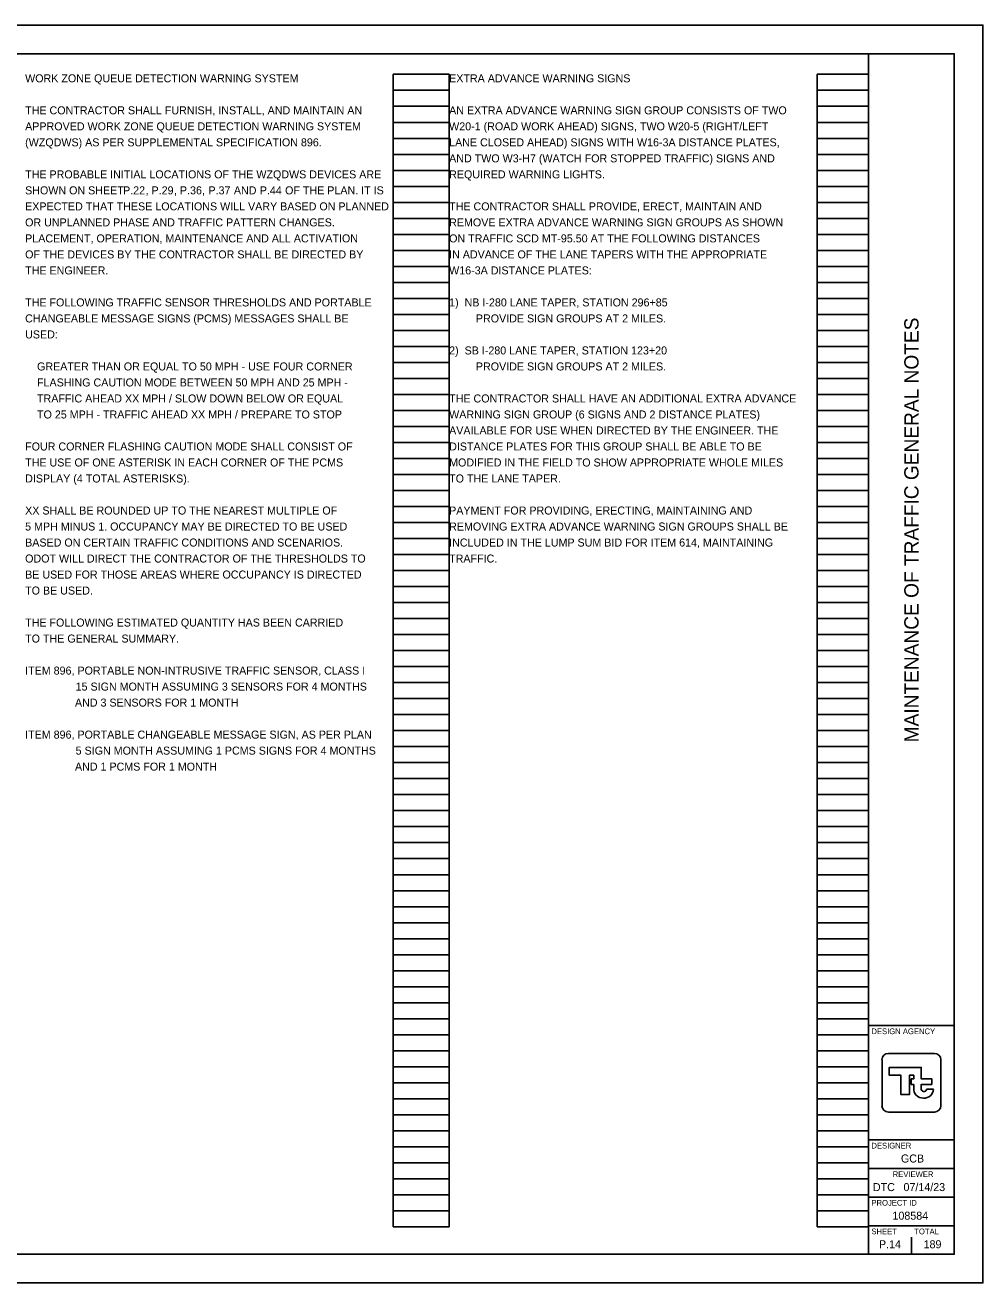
# Model space of a CAD drawing. Extents: x -33.9 to 34, y -0.4 to 22.
# Drawn here: x 17.24 to 34, y 0 to 22 of the extents above; entities that cross this region are included whole.
import ezdxf

# ---------------------------------------------------------------- set-up
doc = ezdxf.new("R2010")
doc.units = 0
for name, color, linetype in [('SH_Border', 7, 'Continuous'), ('SH_Cut_Line', 7, 'Continuous'), ('SH_Data', 7, 'Continuous'), ('SH_Text', 7, 'Continuous')]:
    doc.layers.add(name, color=color, linetype=linetype)

msp = doc.modelspace()

# ---------------------------------------------------------------- linework, layer by layer
at = {"layer": 'SH_Border'}
for p, q in [((32, 0.5), (32, 21.5)), ((32, 4.5), (33.5, 4.5)), ((32, 2.5), (33.5, 2.5)), ((32, 2), (33.5, 2)), ((32, 1.5), (33.5, 1.5)), ((32, 1), (33.5, 1))]:
    msp.add_line(p, q, dxfattribs=at)
msp.add_lwpolyline([(1.5, 21.5), (33.5, 21.5), (33.5, 0.5), (1.5, 0.5)], close=True, dxfattribs=at)
at = {"layer": 'SH_Cut_Line'}
msp.add_lwpolyline([(0, 0), (34, 0), (34, 22), (0, 22)], close=True, dxfattribs=at)
at = {"layer": 'SH_Data'}
for p, q in [((23.68, 0.98), (23.68, 21.14)), ((23.68, 21.14), (24.66, 21.14)), ((24.66, 0.98), (24.66, 21.14)), ((31.1, 0.98), (31.1, 21.14)), ((31.1, 21.14), (32, 21.14)), ((32, 0.98), (32, 21.14)), ((23.68, 20.86), (24.66, 20.86)), ((31.1, 20.86), (32, 20.86)), ((23.68, 20.58), (24.66, 20.58)), ((31.1, 20.58), (32, 20.58)), ((23.68, 20.3), (24.66, 20.3)), ((31.1, 20.3), (32, 20.3)), ((23.68, 20.02), (24.66, 20.02)), ((31.1, 20.02), (32, 20.02)), ((23.68, 19.74), (24.66, 19.74)), ((31.1, 19.74), (32, 19.74)), ((23.68, 19.46), (24.66, 19.46)), ((31.1, 19.46), (32, 19.46)), ((23.68, 19.18), (24.66, 19.18)), ((31.1, 19.18), (32, 19.18)), ((23.68, 18.9), (24.66, 18.9)), ((31.1, 18.9), (32, 18.9)), ((23.68, 18.62), (24.66, 18.62)), ((31.1, 18.62), (32, 18.62)), ((23.68, 18.34), (24.66, 18.34)), ((31.1, 18.34), (32, 18.34)), ((23.68, 18.06), (24.66, 18.06)), ((31.1, 18.06), (32, 18.06)), ((23.68, 17.78), (24.66, 17.78)), ((31.1, 17.78), (32, 17.78)), ((23.68, 17.5), (24.66, 17.5)), ((31.1, 17.5), (32, 17.5)), ((23.68, 17.22), (24.66, 17.22)), ((31.1, 17.22), (32, 17.22)), ((23.68, 16.94), (24.66, 16.94)), ((31.1, 16.94), (32, 16.94)), ((23.68, 16.66), (24.66, 16.66)), ((31.1, 16.66), (32, 16.66)), ((23.68, 16.38), (24.66, 16.38)), ((31.1, 16.38), (32, 16.38)), ((23.68, 16.1), (24.66, 16.1)), ((31.1, 16.1), (32, 16.1)), ((23.68, 15.82), (24.66, 15.82)), ((31.1, 15.82), (32, 15.82)), ((23.68, 15.54), (24.66, 15.54)), ((31.1, 15.54), (32, 15.54)), ((23.68, 15.26), (24.66, 15.26)), ((31.1, 15.26), (32, 15.26)), ((23.68, 14.98), (24.66, 14.98)), ((31.1, 14.98), (32, 14.98)), ((23.68, 14.7), (24.66, 14.7)), ((31.1, 14.7), (32, 14.7)), ((23.68, 14.42), (24.66, 14.42)), ((31.1, 14.42), (32, 14.42)), ((23.68, 14.14), (24.66, 14.14)), ((31.1, 14.14), (32, 14.14)), ((23.68, 13.86), (24.66, 13.86)), ((31.1, 13.86), (32, 13.86)), ((23.68, 13.58), (24.66, 13.58)), ((31.1, 13.58), (32, 13.58)), ((23.68, 13.3), (24.66, 13.3)), ((31.1, 13.3), (32, 13.3)), ((23.68, 13.02), (24.66, 13.02)), ((31.1, 13.02), (32, 13.02)), ((23.68, 12.74), (24.66, 12.74)), ((31.1, 12.74), (32, 12.74)), ((23.68, 12.46), (24.66, 12.46)), ((31.1, 12.46), (32, 12.46)), ((23.68, 12.18), (24.66, 12.18)), ((31.1, 12.18), (32, 12.18)), ((23.68, 11.9), (24.66, 11.9)), ((31.1, 11.9), (32, 11.9)), ((23.68, 11.62), (24.66, 11.62)), ((31.1, 11.62), (32, 11.62)), ((23.68, 11.34), (24.66, 11.34)), ((31.1, 11.34), (32, 11.34)), ((23.68, 11.06), (24.66, 11.06)), ((31.1, 11.06), (32, 11.06)), ((23.68, 10.78), (24.66, 10.78)), ((31.1, 10.78), (32, 10.78)), ((23.68, 10.5), (24.66, 10.5)), ((31.1, 10.5), (32, 10.5)), ((23.68, 10.22), (24.66, 10.22)), ((31.1, 10.22), (32, 10.22)), ((23.68, 9.94), (24.66, 9.94)), ((31.1, 9.94), (32, 9.94)), ((23.68, 9.66), (24.66, 9.66)), ((31.1, 9.66), (32, 9.66)), ((23.68, 9.38), (24.66, 9.38)), ((31.1, 9.38), (32, 9.38)), ((23.68, 9.1), (24.66, 9.1)), ((31.1, 9.1), (32, 9.1)), ((23.68, 8.82), (24.66, 8.82)), ((31.1, 8.82), (32, 8.82)), ((23.68, 8.54), (24.66, 8.54)), ((31.1, 8.54), (32, 8.54)), ((23.68, 8.26), (24.66, 8.26)), ((31.1, 8.26), (32, 8.26)), ((23.68, 7.98), (24.66, 7.98)), ((31.1, 7.98), (32, 7.98)), ((23.68, 7.7), (24.66, 7.7)), ((31.1, 7.7), (32, 7.7)), ((23.68, 7.42), (24.66, 7.42)), ((31.1, 7.42), (32, 7.42)), ((23.68, 7.14), (24.66, 7.14)), ((31.1, 7.14), (32, 7.14)), ((23.68, 6.86), (24.66, 6.86)), ((31.1, 6.86), (32, 6.86)), ((23.68, 6.58), (24.66, 6.58)), ((31.1, 6.58), (32, 6.58)), ((23.68, 6.3), (24.66, 6.3)), ((31.1, 6.3), (32, 6.3)), ((23.68, 6.02), (24.66, 6.02)), ((31.1, 6.02), (32, 6.02)), ((23.68, 5.74), (24.66, 5.74)), ((31.1, 5.74), (32, 5.74)), ((23.68, 5.46), (24.66, 5.46)), ((31.1, 5.46), (32, 5.46)), ((23.68, 5.18), (24.66, 5.18)), ((31.1, 5.18), (32, 5.18)), ((23.68, 4.9), (24.66, 4.9)), ((31.1, 4.9), (32, 4.9)), ((23.68, 4.62), (24.66, 4.62)), ((31.1, 4.62), (32, 4.62)), ((23.68, 4.34), (24.66, 4.34)), ((31.1, 4.34), (32, 4.34)), ((23.68, 4.06), (24.66, 4.06)), ((31.1, 4.06), (32, 4.06)), ((23.68, 3.78), (24.66, 3.78)), ((31.1, 3.78), (32, 3.78)), ((23.68, 3.5), (24.66, 3.5)), ((31.1, 3.5), (32, 3.5)), ((32.75, 3.5), (32.75, 3.5)), ((32.791, 3.415), (32.791, 3.415)), ((33.136, 3.385), (33.015, 3.385)), ((23.68, 3.22), (24.66, 3.22)), ((31.1, 3.22), (32, 3.22)), ((23.68, 2.94), (24.66, 2.94)), ((31.1, 2.94), (32, 2.94)), ((23.68, 2.66), (24.66, 2.66)), ((31.1, 2.66), (32, 2.66)), ((23.68, 2.38), (24.66, 2.38)), ((31.1, 2.38), (32, 2.38)), ((23.68, 2.1), (24.66, 2.1)), ((31.1, 2.1), (32, 2.1)), ((23.68, 1.82), (24.66, 1.82)), ((31.1, 1.82), (32, 1.82)), ((23.68, 1.54), (24.66, 1.54)), ((31.1, 1.54), (32, 1.54)), ((23.68, 1.26), (24.66, 1.26)), ((31.1, 1.26), (32, 1.26)), ((23.68, 0.98), (24.66, 0.98)), ((31.1, 0.98), (32, 0.98)), ((32.375, 0.675), (32.375, 0.675)), ((32.75, 0.5), (32.75, 0.8))]:
    msp.add_line(p, q, dxfattribs=at)
for points in [[(32.348, 4.014), (33.152, 4.014)], [(32.236, 3.099), (32.236, 3.901)], [(32.922, 3.399), (32.922, 3.47), (33.107, 3.47), (33.107, 3.568), (32.922, 3.568), (32.922, 3.768), (32.361, 3.768), (32.361, 3.632), (32.566, 3.632), (32.566, 3.294), (32.715, 3.294), (32.715, 3.63), (32.79, 3.63), (32.79, 3.568), (32.748, 3.568), (32.748, 3.47), (32.79, 3.47), (32.79, 3.415), (32.791, 3.415)], [(33.264, 3.901), (33.264, 3.099)], [(33.152, 2.986), (32.348, 2.986)]]:
    msp.add_lwpolyline(points, dxfattribs=at)
for centre, radius, start, end in [((32.348, 3.901), 0.113, 90, 180), ((33.152, 3.901), 0.113, 360, 90), ((32.949, 3.392), 0.16, 171.8856, 274.8323), ((32.968, 3.392), 0.0473, 171.8856, 350.9243), ((32.976, 3.392), 0.16, 265.1677, 357.3201), ((32.348, 3.099), 0.113, 180, 270), ((33.152, 3.099), 0.113, 270, 360)]:
    msp.add_arc(centre, radius, start, end, dxfattribs=at)

# ---------------------------------------------------------------- texts
msp.add_text('MAINTENANCE OF TRAFFIC GENERAL NOTES', height=0.25, rotation=90, dxfattribs=at).set_placement((32.875, 9.455))
for s, height, p in [('DESIGN AGENCY', 0.1, (32.05, 4.35)), ('DESIGNER', 0.1, (32.05, 2.35)), ('GCB', 0.14, (32.566, 2.105)), ('REVIEWER', 0.1, (32.422, 1.85)), ('DTC', 0.14, (32.076, 1.605)), ('07/14/23', 0.14, (32.611, 1.605)), ('PROJECT ID', 0.1, (32.05, 1.35)), ('108584', 0.14, (32.418, 1.105)), ('SHEET', 0.1, (32.05, 0.85)), ('TOTAL', 0.1, (32.8, 0.85)), ('P.14', 0.14, (32.182, 0.605)), ('189', 0.14, (32.963, 0.605))]:
    msp.add_text(s, height=height, dxfattribs=at).set_placement(p)
at = {"layer": 'SH_Text'}
for s, p in [('WORK ZONE QUEUE DETECTION WARNING SYSTEM', (17.24, 21)), ('EXTRA ADVANCE WARNING SIGNS', (24.66, 21)), ('THE CONTRACTOR SHALL FURNISH, INSTALL, AND MAINTAIN AN', (17.24, 20.44)), ('AN EXTRA ADVANCE WARNING SIGN GROUP CONSISTS OF TWO', (24.66, 20.44)), ('APPROVED WORK ZONE QUEUE DETECTION WARNING SYSTEM', (17.24, 20.16)), ('W20-1 (ROAD WORK AHEAD) SIGNS, TWO W20-5 (RIGHT/LEFT', (24.66, 20.16)), ('(WZQDWS) AS PER SUPPLEMENTAL SPECIFICATION 896.', (17.24, 19.88)), ('LANE CLOSED AHEAD) SIGNS WITH W16-3A DISTANCE PLATES,', (24.66, 19.88)), ('AND TWO W3-H7 (WATCH FOR STOPPED TRAFFIC) SIGNS AND', (24.66, 19.6)), ('THE PROBABLE INITIAL LOCATIONS OF THE WZQDWS DEVICES ARE', (17.24, 19.32)), ('REQUIRED WARNING LIGHTS.', (24.66, 19.32)), ('SHOWN ON SHEET ', (17.24, 19.04)), ('P.22', (18.954, 19.04)), ('P.29', (19.452, 19.04)), (', P.36, ', (19.845, 19.04)), ('P.37', (20.448, 19.04)), (' AND ', (20.841, 19.04)), ('P.44', (21.346, 19.04)), ('OF THE PLAN. IT IS ', (21.789, 19.04)), (', ', (19.347, 19.04)), ('EXPECTED THAT THESE LOCATIONS WILL VARY BASED ON PLANNED', (17.24, 18.76)), ('THE CONTRACTOR SHALL PROVIDE, ERECT, MAINTAIN AND', (24.66, 18.76)), ('OR UNPLANNED PHASE AND TRAFFIC PATTERN CHANGES.', (17.24, 18.48)), ('REMOVE EXTRA ADVANCE WARNING SIGN GROUPS AS SHOWN', (24.66, 18.48)), ('PLACEMENT, OPERATION, MAINTENANCE AND ALL ACTIVATION', (17.24, 18.2)), ('ON TRAFFIC SCD MT-95.50 AT THE FOLLOWING DISTANCES', (24.66, 18.2)), ('OF THE DEVICES BY THE CONTRACTOR SHALL BE DIRECTED BY', (17.24, 17.92)), ('IN ADVANCE OF THE LANE TAPERS WITH THE APPROPRIATE', (24.66, 17.92)), ('THE ENGINEER.', (17.24, 17.64)), ('W16-3A DISTANCE PLATES:', (24.66, 17.64)), ('THE FOLLOWING TRAFFIC SENSOR THRESHOLDS AND PORTABLE', (17.24, 17.08)), ('1)  NB I-280 LANE TAPER, STATION 296+85', (24.66, 17.08)), ('CHANGEABLE MESSAGE SIGNS (PCMS) MESSAGES SHALL BE', (17.24, 16.8)), ('         PROVIDE SIGN GROUPS AT 2 MILES.', (24.66, 16.8)), ('USED:', (17.24, 16.52)), ('2)  SB I-280 LANE TAPER, STATION 123+20', (24.66, 16.24)), ('    GREATER THAN OR EQUAL TO 50 MPH - USE FOUR CORNER', (17.24, 15.96)), ('         PROVIDE SIGN GROUPS AT 2 MILES.', (24.66, 15.96)), ('    FLASHING CAUTION MODE BETWEEN 50 MPH AND 25 MPH -', (17.24, 15.68)), ('    TRAFFIC AHEAD XX MPH / SLOW DOWN BELOW OR EQUAL', (17.24, 15.4)), ('THE CONTRACTOR SHALL HAVE AN ADDITIONAL EXTRA ADVANCE', (24.66, 15.4)), ('    TO 25 MPH - TRAFFIC AHEAD XX MPH / PREPARE TO STOP', (17.24, 15.12)), ('WARNING SIGN GROUP (6 SIGNS AND 2 DISTANCE PLATES)', (24.66, 15.12)), ('AVAILABLE FOR USE WHEN DIRECTED BY THE ENGINEER. THE', (24.66, 14.84)), ('FOUR CORNER FLASHING CAUTION MODE SHALL CONSIST OF', (17.24, 14.56)), ('DISTANCE PLATES FOR THIS GROUP SHALL BE ABLE TO BE', (24.66, 14.56)), ('THE USE OF ONE ASTERISK IN EACH CORNER OF THE PCMS', (17.24, 14.28)), ('MODIFIED IN THE FIELD TO SHOW APPROPRIATE WHOLE MILES', (24.66, 14.28)), ('DISPLAY (4 TOTAL ASTERISKS).', (17.24, 14)), ('TO THE LANE TAPER.', (24.66, 14)), ('XX SHALL BE ROUNDED UP TO THE NEAREST MULTIPLE OF', (17.24, 13.44)), ('PAYMENT FOR PROVIDING, ERECTING, MAINTAINING AND', (24.66, 13.44)), ('5 MPH MINUS 1. OCCUPANCY MAY BE DIRECTED TO BE USED', (17.24, 13.16)), ('REMOVING EXTRA ADVANCE WARNING SIGN GROUPS SHALL BE', (24.66, 13.16)), ('BASED ON CERTAIN TRAFFIC CONDITIONS AND SCENARIOS.', (17.24, 12.88)), ('INCLUDED IN THE LUMP SUM BID FOR ITEM 614, MAINTAINING', (24.66, 12.88)), ('ODOT WILL DIRECT THE CONTRACTOR OF THE THRESHOLDS TO', (17.24, 12.6)), ('TRAFFIC.', (24.66, 12.6)), ('BE USED FOR THOSE AREAS WHERE OCCUPANCY IS DIRECTED', (17.24, 12.32)), ('TO BE USED.', (17.24, 12.04)), ('THE FOLLOWING ESTIMATED QUANTITY HAS BEEN CARRIED', (17.24, 11.48)), ('TO THE GENERAL SUMMARY.', (17.24, 11.2)), ('ITEM 896, PORTABLE NON-INTRUSIVE TRAFFIC SENSOR, CLASS I', (17.24, 10.64)), ('                 15 SIGN MONTH ASSUMING 3 SENSORS FOR 4 MONTHS', (17.24, 10.36)), ('      AND 3 SENSORS FOR 1 MONTH', (17.8, 10.08)), ('ITEM 896, PORTABLE CHANGEABLE MESSAGE SIGN, AS PER PLAN ', (17.24, 9.52)), ('                 5 SIGN MONTH ASSUMING 1 PCMS SIGNS FOR 4 MONTHS', (17.24, 9.24)), ('      AND 1 PCMS FOR 1 MONTH', (17.8, 8.96))]:
    msp.add_text(s, height=0.14, dxfattribs=at).set_placement(p)

doc.saveas('drawing.dxf')
